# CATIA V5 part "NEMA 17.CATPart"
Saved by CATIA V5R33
Part number: NEMA 17
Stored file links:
  C:\Users\Ryzen5700u\Desktop\robot_cicloidale_singolo\Assieme_robot_cicloidale_singolo\NEMA 17.CATPart

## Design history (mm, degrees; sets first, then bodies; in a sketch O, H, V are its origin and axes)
Body1 "Solido1" (main body)
  Solid1: solid without history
